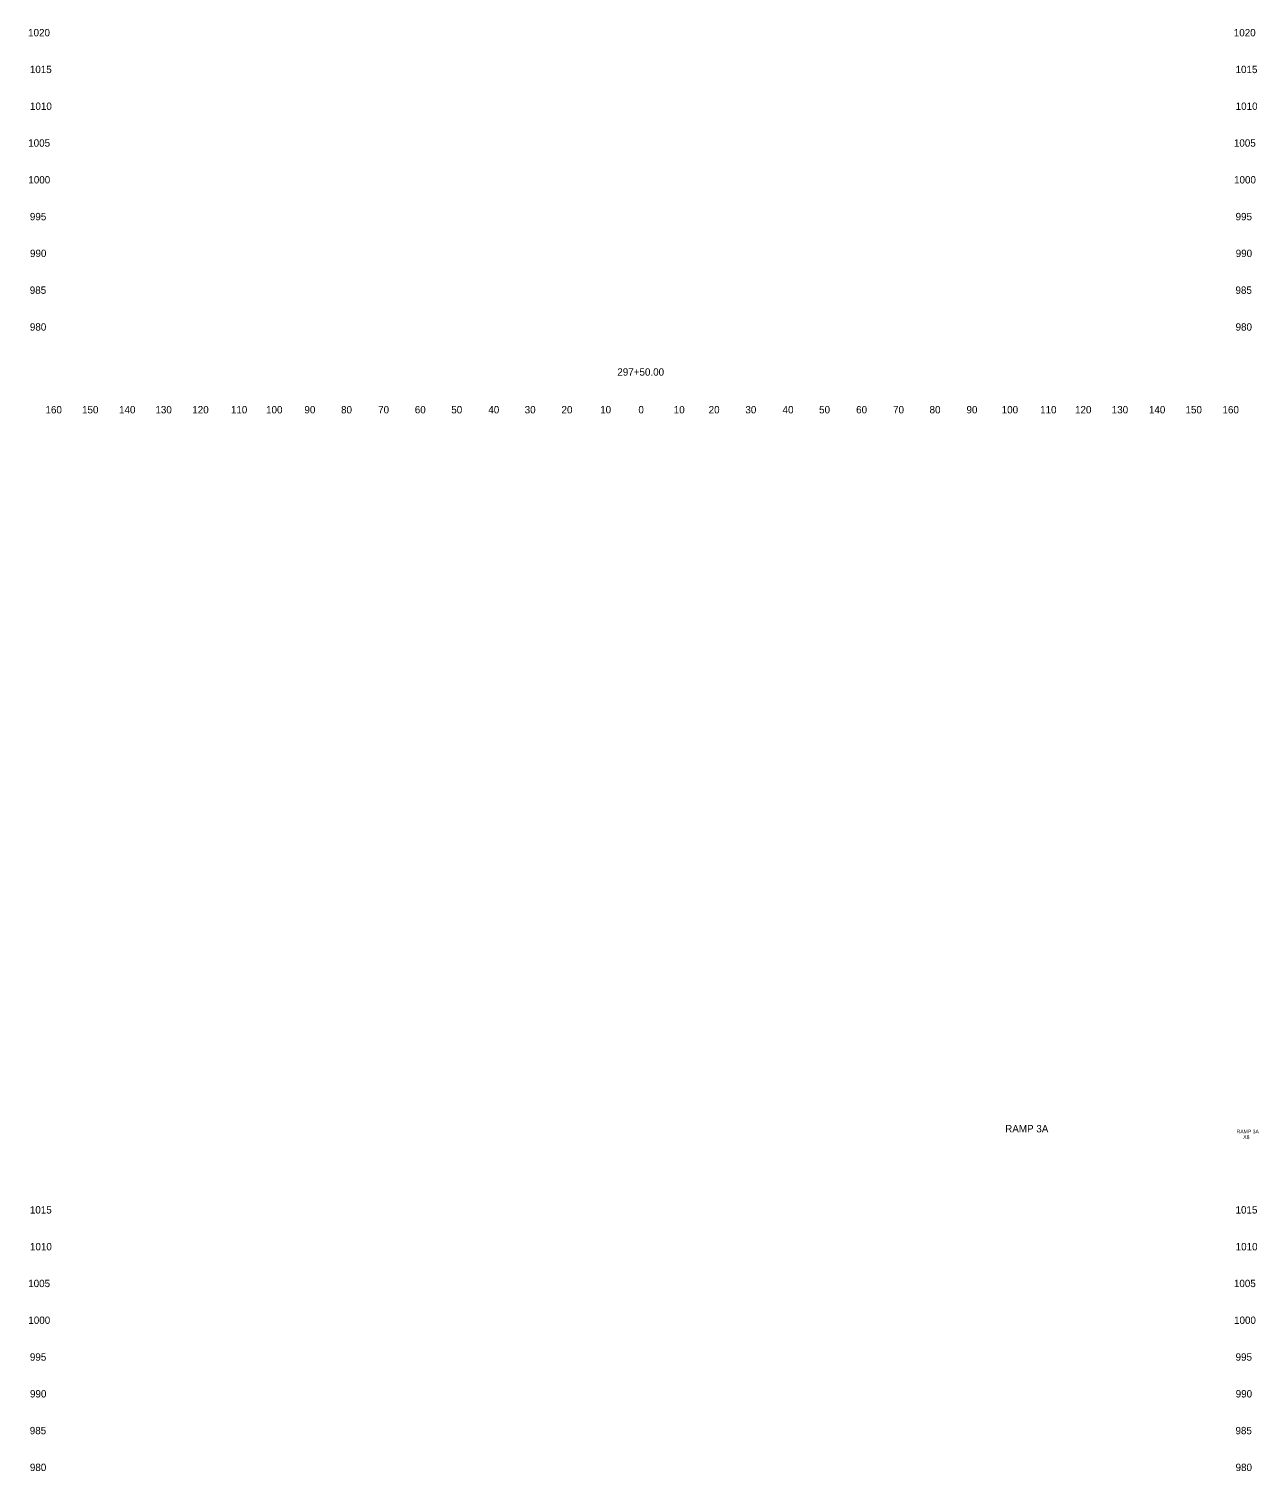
# Model space of a CAD drawing. Extents: x 4286 to 5843, y 4997 to 8804.
# Drawn here: x 4993.6 to 5327.8, y 7910 to 8302 of the extents above; entities that cross this region are included whole.
import ezdxf

# ---------------------------------------------------------------- set-up
doc = ezdxf.new("R2010")
doc.units = 0
for name, color, linetype in [('RD_SHT_ID', 7, 'Continuous'), ('RD_XS_TX_Offset', 7, 'Continuous'), ('RD_XS_TX_Station', 7, 'Continuous')]:
    doc.layers.add(name, color=color, linetype=linetype)

msp = doc.modelspace()

# ---------------------------------------------------------------- texts
at = {"layer": 'RD_SHT_ID'}
for s, height, p in [('RAMP 3A', 2, (5259.02, 8002.06)), ('RAMP 3A', 1, (5321.93, 8001.8)), ('X8', 1, (5323.74, 8000.3))]:
    msp.add_text(s, height=height, dxfattribs=at).set_placement(p)
at = {"layer": 'RD_XS_TX_Offset'}
for s, p in [('1020', (4993.37, 8300)), ('1020', (5321.17, 8300)), ('1015', (4993.85, 8290)), ('1015', (5321.65, 8290)), ('1010', (4993.88, 8280)), ('1010', (5321.68, 8280)), ('1005', (4993.4, 8270)), ('1005', (5321.2, 8270)), ('1000', (4993.44, 8260)), ('1000', (5321.24, 8260)), ('995', (4993.86, 8250)), ('995', (5321.66, 8250)), ('990', (4993.89, 8240)), ('990', (5321.69, 8240)), ('985', (4993.83, 8230)), ('985', (5321.63, 8230)), ('980', (4993.86, 8220)), ('980', (5321.66, 8220)), ('160', (4998.1, 8197.5)), ('150', (5008.04, 8197.5)), ('140', (5018.1, 8197.5)), ('130', (5027.99, 8197.5)), ('120', (5038.01, 8197.5)), ('110', (5048.51, 8197.5)), ('100', (5058.07, 8197.5)), ('90', (5068.5, 8197.5)), ('80', (5078.46, 8197.5)), ('70', (5088.54, 8197.5)), ('60', (5098.5, 8197.5)), ('50', (5108.43, 8197.5)), ('40', (5118.5, 8197.5)), ('30', (5128.39, 8197.5)), ('20', (5138.4, 8197.5)), ('10', (5148.91, 8197.5)), ('0', (5159.3, 8197.5)), ('0', (5159.3, 8197.5)), ('10', (5168.91, 8197.5)), ('20', (5178.4, 8197.5)), ('30', (5188.39, 8197.5)), ('40', (5198.5, 8197.5)), ('50', (5208.43, 8197.5)), ('60', (5218.5, 8197.5)), ('70', (5228.54, 8197.5)), ('80', (5238.46, 8197.5)), ('90', (5248.5, 8197.5)), ('100', (5258.07, 8197.5)), ('110', (5268.51, 8197.5)), ('120', (5278.01, 8197.5)), ('130', (5287.99, 8197.5)), ('140', (5298.1, 8197.5)), ('150', (5308.04, 8197.5)), ('160', (5318.1, 8197.5)), ('1015', (4993.85, 7980)), ('1015', (5321.65, 7980)), ('1010', (4993.88, 7970)), ('1010', (5321.68, 7970)), ('1005', (4993.4, 7960)), ('1005', (5321.2, 7960)), ('1000', (4993.44, 7950)), ('1000', (5321.24, 7950)), ('995', (4993.86, 7940)), ('995', (5321.66, 7940)), ('990', (4993.89, 7930)), ('990', (5321.69, 7930)), ('985', (4993.83, 7920)), ('985', (5321.63, 7920)), ('980', (4993.86, 7910)), ('980', (5321.66, 7910))]:
    msp.add_text(s, height=2, dxfattribs=at).set_placement(p)
at = {"layer": 'RD_XS_TX_Station'}
msp.add_text('297+50.00', height=2, dxfattribs=at).set_placement((5153.57, 8207.76))

doc.saveas('drawing.dxf')
